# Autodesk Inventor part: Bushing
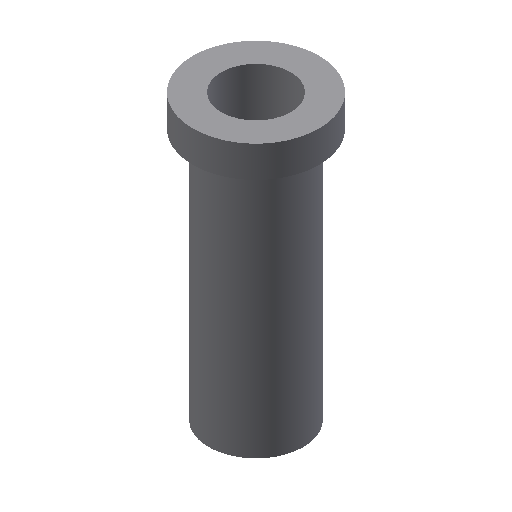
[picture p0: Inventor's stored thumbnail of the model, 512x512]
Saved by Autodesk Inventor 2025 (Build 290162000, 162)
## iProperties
Shininess: 77.0
Length Units: 11269
Angle Units: 11279
Time Units: 11290
Mass Units: 11283
Length Display Precision: 3
Angle Display Precision: 2
Created: 2002-02
Part Number: Bushing
Document SubType Name: Modeling
Designer: ***
Density: 1 g/cm^3
Material: Generic
Appearance: Default
Density: 0.0
Volumn: 0.0
Area: 0.0
PropertySet Name: Model Information
Control State: 0
Master: False
Checked Out: False
Author: ***
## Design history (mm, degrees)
sketch "Sketch2"
  geometry: C1 r 10 at (0, 0); 1 further point
  constraints: 1 centre point, 1 coincident
  dimensions: "d8" = 20 diameter of C1
extrude "Extrusion1" new body sketch "Sketch2" distance "d6" = 5; taper "d7" = 0 deg
sketch "Sketch4"
  geometry: C1 r 7.5 at (0, 0); 1 further point
  constraints: 1 centre point, 1 coincident
  dimensions: "d9" = 15 diameter of C1
extrude "Extrusion2" join sketch "Sketch4" distance "d10" = 40; taper "d11" = 0 deg
sketch "Sketch5"
  geometry: C1 r 5.5 at (0, 0); 1 further point
  constraints: 1 centre point, 1 coincident
  dimensions: "d12" = 11 diameter of C1
extrude "Extrusion3" cut sketch "Sketch5" distance "d13" = 57.75; taper "d14" = 0 deg
body "Solid2"
